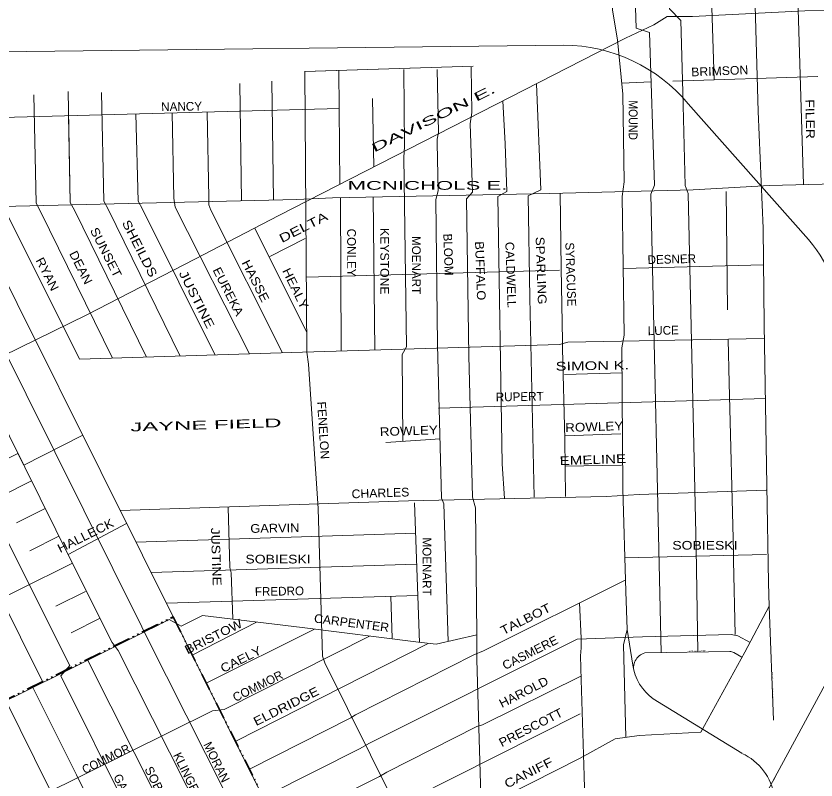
# Model space of a CAD drawing. Extents: x 34705 to 138605, y 34275 to 143551.
# Drawn here: x 95843 to 102735, y 126812 to 133396 of the extents above; entities that cross this region are included whole.
import ezdxf
from ezdxf.enums import TextEntityAlignment as Align

# ---------------------------------------------------------------- set-up
doc = ezdxf.new("R2010")
doc.units = 0
doc.header["$LTSCALE"] = 30
doc.linetypes.add('DASH_DOUBLE_DOT', pattern=[9.2, 5, -1.2, 0.3, -1.2, 0.3, -1.2])
for name, color, linetype, lineweight in [('1', 7, 'Continuous', 13), ('11', 7, 'Continuous', 13), ('50', 7, 'Continuous', 13), ('59', 7, 'DASH_DOUBLE_DOT', 106)]:
    doc.layers.add(name, color=color, linetype=linetype, lineweight=lineweight)
doc.layers.add('12', color=7, linetype='Continuous')

msp = doc.modelspace()

# ---------------------------------------------------------------- linework, layer by layer
at = {"layer": '1'}
for p, q in [((102549.39, 134581.2), (102627.53, 131943.02)), ((98327.75, 132918.07), (99781.24, 132964.59)), ((98330.03, 132918.14), (99781.24, 132964.59)), ((98625.01, 132927.58), (98631.65, 131943.94)), ((98048, 132833.55), (98061.13, 131808.84)), ((101061.68, 132816.44), (101314.5, 132828.78)), ((101502.89, 132835.92), (102751.71, 132874.45)), ((97772.33, 132814.31), (97785.63, 131802.55)), ((98913.49, 132686.05), (98926.92, 132095.21)), ((101960.33, 131884.41), (101973.15, 130864.72)), ((98637.77, 131830.64), (98644.22, 130508)), ((98920.06, 131836.21), (98932.87, 130516.62)), ((97899.81, 131568.1), (98347.97, 130668.5)), ((98028.7, 131323.65), (98332.77, 131480.08)), ((101075.91, 131220.45), (102283.32, 131251.08)), ((98345.8, 131145.49), (100526.42, 131206.32)), ((100567.68, 130307.94), (101064.21, 130321.13)), ((99481.71, 130016.81), (102299.09, 130099.57)), ((94897.78, 130008.58), (96075.01, 127654.96)), ((100570.04, 129777.26), (101054.19, 129795.2)), ((99029.95, 129721.33), (99496.07, 129753.64)), ((100573.75, 129516.97), (101058.54, 129525.79)), ((95721.67, 129261.64), (95976.32, 129390.62)), ((99275.71, 129200.52), (99317.93, 127998.54)), ((95847.62, 129027.04), (96094.58, 129152.13)), ((95961.44, 128786.29), (96212.84, 128913.63)), ((96876.15, 128861.4), (99284.83, 128940.69)), ((101084.6, 128726.26), (102309.57, 128756.68)), ((97006.36, 128600.16), (99294.27, 128671.97)), ((96185.82, 128311.29), (96442.1, 128437.3)), ((97138.31, 128335.44), (99303.76, 128401.89)), ((99073.35, 128394.82), (99083.38, 128033.33)), ((102367.68, 127328.44), (102332.17, 128310.71)), ((96316.78, 128079.72), (96568.08, 128207)), ((97360.79, 127889.1), (97915.38, 128173.24)), ((97481.37, 127646.97), (98415.73, 128112.08)), ((101157.23, 127802.13), (101109.27, 128110.29)), ((97737.66, 127147.84), (99394.8, 127989.84)), ((101259.02, 127906.69), (101992.73, 127919.08)), ((102027.16, 127909.59), (102097.27, 127871.32)), ((96460.12, 127843.12), (97659.84, 125468.45)), ((101333.46, 127512.66), (102094.78, 127042.89)), ((98232.79, 126139.68), (100704.52, 127382.49))]:
    msp.add_line(p, q, dxfattribs=at)
for points in [[(101951.16, 142542.84), (102026.05, 139982.57), (102027.19, 139747.46), (102070.92, 138206.13), (102096.57, 137212.1), (102088.55, 137181.64), (102088.55, 137040.55), (102101.37, 136527.5), (102127.02, 135937.49), (102139.84, 135437.27), (102152.66, 135020.41), (102203.95, 133878.88), (102210.36, 133484.48), (102236.01, 132573.81), (102280.88, 131566.95), (102287.29, 130736.46), (102312.94, 129351.22), (102325.76, 128511.11), (102332.17, 128310.71), (102120.61, 127913.09), (101741.51, 127224.19)], [(100686.61, 142506.77), (100763.07, 139892.78), (100750.25, 139726.04), (100764.21, 139657.68), (100807.95, 138116.35), (100833.59, 137122.31), (100846.42, 136910.68), (100878.47, 135865.34), (100910.53, 135087.76), (100948.99, 133965.46), (100981.05, 133446), (101025.93, 133189.47), (101070.8, 132721.32), (101083.62, 131967.78), (101064.39, 131839.52), (101083.62, 130646.68), (101062.79, 130537.65), (101070.8, 129322.37), (101096.45, 128437.36), (101109.27, 128110.29), (101077.21, 127975.62), (101097.94, 127180.93)], [(95349.32, 142354.53), (95401.65, 141128.32), (95400.24, 140999.04), (95387.42, 140890.02), (95432.3, 139735.66), (95451.53, 139575.33), (95560.52, 137037.34), (95573.34, 136928.31), (95675.92, 134412.77), (95682.33, 134348.64), (95703.17, 132562.59), (95727.2, 131801.04), (95752.85, 131717.67), (96389.41, 130437.7)], [(90104.12, 141802.04), (90220.45, 141642.8), (90630.68, 140864.96), (91512.35, 139205.15), (92694.04, 136986.48), (92755.27, 136888.48), (93165.5, 136080.02), (94792.8, 133011.51), (95209.51, 132197.05), (95491.6, 131639.1), (98371.75, 125860.89), (98410.22, 125771.11), (99474.45, 123667.62), (99570.62, 123609.9), (99859.12, 123007.06), (99871.94, 122930.11), (99923.24, 122823.63)], [(101012.58, 139829.49), (101029.14, 139139.23), (101082.02, 137220.12), (101062.79, 137143.16), (101184.6, 133292.08), (101299.99, 133253.61), (101344.87, 131938.91), (101312.82, 131861.96), (101402.37, 127909.11)], [(101345.73, 139838.97), (101362.51, 139139.23), (101415.39, 137239.36), (101357.69, 137162.4), (101473.09, 133458.83), (101569.26, 133356.22), (101588.49, 132740.56)], [(101686.97, 139848.67), (101702.3, 139209.78), (101748.77, 137239.36), (101710.3, 137168.81), (101787.23, 135177.54), (101787.23, 135074.93), (101857.44, 132846.86)], [(95130.25, 130321.18), (95381.61, 130325.96), (95576.64, 130393.64), (96452.28, 130819.66), (97383.65, 131301.42), (98108.05, 131675.68), (101094.19, 133205.57), (101336.98, 133321.03), (101452.41, 133392.7), (101671.32, 133392.7), (102639.49, 133440.47), (105214.69, 133516.12), (106171.95, 133548.83)], [(94232.64, 133482.78), (95119.76, 131760.95), (95164.64, 131671.17), (95177.46, 131645.52), (96927.67, 128132.74), (96972.55, 128036.55), (98146.33, 125708.92)], [(98330.03, 132918.14), (98349.32, 130499.17), (98362.14, 130396.56), (98445.49, 129152.42), (98483.95, 127879.42), (98503.19, 127821.7), (99879.07, 125050.88)], [(99182.76, 132936.16), (99189.17, 132269.2), (99182.76, 132179.41), (99208.4, 130544.07), (99169.93, 130479.94), (99176.34, 129736.01)], [(99471.25, 132936.16), (99484.08, 132391.05), (99471.25, 132333.33), (99471.25, 132301.26), (99480.86, 131890.82), (99458.43, 131813.87), (99474.45, 130563.31), (99509.72, 129242.2), (99528.95, 129190.9), (99564.89, 128005.86)], [(99762.95, 132955.4), (99769.36, 132564.2), (99756.54, 132468), (99775.77, 131878), (99724.48, 131820.28), (99743.72, 130467.11), (99775.77, 129248.61), (99801.42, 129158.83), (99814.24, 128067.01), (99814.24, 127848.96), (99929.64, 123858.4)], [(100326.11, 132812.06), (100365.59, 131897.24), (100256.6, 131845.93), (100269.42, 130967.33), (100307.89, 129248.61)], [(95996.47, 132718.12), (96015.7, 131781.8), (96054.17, 131711.26), (96673.76, 130446.63)], [(96290.94, 132745.63), (96310.61, 131788.21), (96349.07, 131717.67), (96967.29, 130455.85)], [(96579.87, 132737.36), (96599.11, 131801.04), (96637.57, 131730.49), (97257.6, 130464.97)], [(101588.49, 132740.56), (101607.72, 131935.71), (101633.37, 131865.17), (101703.89, 128806.11), (101716.07, 127914.4)], [(100037.35, 132664.12), (100057.86, 132294.85), (100070.68, 131884.41), (99993.75, 131839.52), (100032.21, 129537.21), (100050.6, 129236.8)], [(95061.76, 132493.51), (95189.67, 132557.48), (95695.48, 132563.3), (95724.55, 132522.59), (98630.08, 132598.19)], [(96874.42, 132552.51), (96894.01, 131801.04), (96932.48, 131730.49), (97557.09, 130474.37)], [(97188.76, 132560.69), (97201.74, 131826.69), (97214.57, 131749.73), (97853.59, 130483.68)], [(97490.05, 132568.53), (97503.06, 131833.1), (97503.06, 131768.97), (97522.3, 131724.08), (98137.83, 130492.6)], [(96295.22, 132537.44), (96310.61, 131788.21), (96349.07, 131717.67), (96967.29, 130455.85)], [(89151.86, 131581.25), (90043.44, 131623.47), (90222.81, 131655.13), (92165.54, 131723.74), (95067.12, 131739.57), (95420.59, 131739.57), (95721.29, 131755.4), (98262.81, 131813.45), (98568.79, 131829.28), (100441.63, 131866.22), (101676.12, 131897.89), (102335.57, 131934.83), (102900.06, 131950.66), (106145.2, 132049.31), (106275.51, 132066.69), (107380.6, 132092.9)], [(94731.9, 131962.97), (95512.95, 130409.57), (95517.24, 130316.41), (96318.63, 128700.3), (96671.23, 127998.07), (96722.52, 127927.52), (97903.51, 125588.89)], [(100532.11, 131868.54), (100538.69, 131223.86), (100551.51, 130595.37), (100551.51, 130531.24), (100570.74, 129748.84), (100577.15, 129255.03)], [(96389.41, 130437.7), (98311.05, 130498.04), (100525.34, 130564.93), (100596.11, 130586.71), (102289.51, 130616.89)], [(101979.56, 130608.2), (101985.98, 130236.24), (102024.44, 128780.46), (102024.44, 128703.5), (102037.83, 128065.55)], [(95131.5, 130138.02), (96305.8, 127799.26), (96228.87, 127709.48), (97384.45, 125389.53), (97653.72, 124838), (97660.13, 124818.77), (97807.58, 124652.02), (97945.42, 124408.33), (97983.89, 124363.43), (98567.3, 123196.24), (98592.94, 123119.29), (99163.52, 121977.75)], [(92031.01, 127728.04), (93759.06, 128587.98), (93811.76, 128481.61), (94481.31, 128812.57), (94426.71, 128922.17), (95859.1, 129627), (95908.95, 129526.46), (96411.7, 129779.99)], [(96739.51, 129135.51), (99224.35, 129218.36), (100928.22, 129256.38), (101210.57, 129273.76), (102305.23, 129308.53)], [(97669.75, 129162.04), (97685.77, 128644.19), (97695.39, 128597.69), (97709.82, 128201.68)], [(92783.26, 126916.28), (92904.03, 126982.73), (93966.1, 127504.16), (94843.56, 127934.34), (94939.13, 127990.83), (96329.05, 128679.54), (96291.19, 128755.63), (96795.84, 129022.52)], [(97859.28, 126908.85), (98728.06, 127347.73), (98767.15, 127373.8), (99787.96, 127890.89), (99870.49, 127925.65), (101091.12, 128533.99)], [(100698, 128338.07), (100711.78, 128034.94), (100711.78, 127951.57), (100705.37, 127881.03), (100711.78, 127675.81), (100737.43, 126848.51), (100788.72, 124975.88)], [(93161.76, 126203.92), (93402.49, 126330.93), (96243.37, 127734.46), (97162.1, 128195.06), (97266.35, 128138.57), (97448.79, 128229.82), (98308.88, 128125.53), (99310.14, 127999.52), (99462.17, 127982.14), (99814.28, 128063.42)], [(91804.4, 124602.41), (92258.1, 124821.03), (92523.21, 124902.16), (93277.23, 125281.76), (93553.22, 125429.66), (93553.22, 125434.59), (94282.6, 125789.54), (94282.6, 125863.49), (95554.1, 126489.58), (95692.09, 126494.51), (97536.49, 127409), (97635.06, 127418.86), (98887.4, 128052.72)], [(94580.43, 125251.39), (95217.74, 125572.62), (95306.45, 125478.96), (95927.41, 125784.61), (96060.48, 125720.52), (97920.9, 126635.01), (98014.54, 126684.31), (98807.99, 127083.63), (98881.91, 127128), (100678.27, 128025.23), (101240.09, 128044.95), (102003.97, 128064.67), (102063.11, 128054.81), (102166.81, 127997.19)], [(98106.89, 126404.8), (98975.66, 126843.68), (99036.47, 126878.44), (99814.02, 127273.86), (99861.81, 127286.89), (100708.86, 127708.39)], [(95987.8, 127608.19), (96363.5, 126856.53), (97169, 125225.82)], [(95754.45, 127497.84), (96126.29, 126747.51), (96164.76, 126676.96), (96932.73, 125109.03)], [(93365.26, 123330.55), (93956.1, 123637.65), (98379.23, 125824.05), (100702.91, 126999.82), (101003.53, 127167.44), (101210.52, 127197.01), (101741.51, 127224.19), (101741.31, 127223.78)]]:
    msp.add_lwpolyline(points, dxfattribs=at)
for centre, radius, start, end in [((101295.27, 127780.5), 131.28, 106.02889, 200.57915), ((101990.69, 127844.45), 74.66, 60.75806, 88.43815), ((101583.83, 127863.47), 430.99, 188.18156, 234.48459), ((101902.2, 126605.66), 476.88, 7.643, 66.0502)]:
    msp.add_arc(centre, radius, start, end, dxfattribs=at)
at = {"layer": '50'}
for p, q in [((95678.87, 133088.07), (100563.97, 133144.41)), ((101632.92, 132640.31), (102671.13, 131471.39)), ((102370.3, 126813.99), (102381.36, 126834.49)), ((102370.5, 126812.45), (102381.41, 126832.69))]:
    msp.add_line(p, q, dxfattribs=at)
for points in [[(102381.37, 126834.33), (103625.89, 129138.56), (106032.14, 133515.49), (107949.49, 136936.41), (108177.8, 137385.22), (110790.54, 142647.36)], [(95605.01, 114875.68), (95898.83, 115205.5), (96253.46, 115672.66), (96427.21, 115978.34), (97040.49, 117123.56), (97587.96, 118151.92), (98941.92, 120620.79), (100322.5, 123162.08), (102317.07, 126715.28), (102381.36, 126834.49)]]:
    msp.add_lwpolyline(points, dxfattribs=at)
for centre, radius, start, end in [((100556.78, 131743.75), 1400.67, 39.79829, 89.70596), ((101213, 130316.33), 1860.19, 10.55696, 38.38477)]:
    msp.add_arc(centre, radius, start, end, dxfattribs=at)
at = {"layer": '59', "lineweight": 35}
msp.add_line((91991.09, 125628.99), (97197.73, 128215.55), dxfattribs=at)
msp.add_lwpolyline([(91983.3, 125629.39), (97196.01, 128218.97), (98041.3, 126530.08), (101064.01, 126630.97), (101215.3, 121377.77), (100630.88, 121363.11), (101602.13, 119372.61), (97881.18, 117512.12), (95736.43, 121807.31), (94620.91, 121239.02)], close=True, dxfattribs=at)
msp.add_lwpolyline([(97196.01, 128218.97), (97196.01, 128218.97), (98041.3, 126530.08), (98041.31, 126530.08)], dxfattribs=at)

# ---------------------------------------------------------------- texts
at = {"layer": '11'}
for s, height, rotation, width, p in [('BRIMSON', 75, 2.298, 1.05, (101907.13, 132885.43)), ('DAVISON E.', 75, 26.403, 2.05, (99454.97, 132480.58)), ('MOUND', 75, 270, 0.9, (101122.46, 132498.53)), ('FILER', 75, 270.997, 1.2, (102647.36, 132506.9)), ('DELTA ', 75, 26.946, 1.4, (98352.83, 131550.32)), ('SHEILDS', 75, 296.947, 1.25, (96875.02, 131375.66)), ('SUNSET', 75, 296.944, 1.15, (96583.87, 131341.74)), ('KEYSTONE', 75, 270, 1.05, (98981.69, 131282.31)), ('BUFFALO', 75, 271.999, 1.1, (99806.39, 131198.96)), ('CALDWELL', 75, 271.999, 1.05, (100068.16, 131164.9)), ('SPARLING', 75, 272, 1.15, (100329.87, 131200.7)), ('DEAN', 75, 296.948, 1.1, (96367.88, 131211.71)), ('RYAN', 75, 296.949, 1.1, (96078.81, 131154.65)), ('HASSE', 75, 296.944, 1.15, (97873.36, 131096.41)), ('JUSTINE', 75, 296.947, 1.3, (97366.94, 130937.2)), ('EUREKA', 75, 296.947, 1.1, (97637.61, 131005.01)), ('HEALY', 75, 295.947, 1.15, (98216.92, 131031.44)), ('SIMON K. ', 75, 1.002, 1.4, (100827.91, 130345.74)), ('FENELON', 75, 273.694, 1.05, (98452.81, 129823.11)), ('JAYNE FIELD', 75, 1.665, 2.05, (97479.83, 129834.76)), ('ROWLEY ', 75, 1.999, 1.15, (99244.25, 129784.48)), ('ROWLEY ', 75, 2, 1.15, (100841.37, 129819.99)), ('EMELINE ', 75, 2, 1.3, (100831.96, 129535.87)), ('CHARLES', 75, 2.001, 1.05, (98983.78, 129248.21)), ('HALLECK', 75, 26.414, 1.15, (96458.5, 128884.39)), ('JUSTINE', 75, 271.998, 1.2, (97530.08, 128734.8)), ('GARVIN', 75, 1.002, 1.1, (98073.41, 128945.36)), ('TALBOT', 75, 26.769, 1.2, (100249.13, 128165.47)), ('CARPENTER', 75, 352.739, 1.05, (98729.24, 128129.11)), ('BRISTOW', 75, 26.56, 1.15, (97560.7, 128015.35)), ('CASMERE', 75, 26.77, 1.05, (100288.91, 127876.61)), ('CAELY', 75, 26.431, 1.15, (97796.77, 127818.09)), ('MT. ELLIOTT    ', 14.06, 1.539, 1.25, (101726.31, 127913.67)), ('HAROLD', 75, 26.992, 1.1, (100233.37, 127536.23)), ('ELDRIDGE', 75, 26.657, 1.2, (98186.42, 127414.28)), ('MT. ELLIOTT', 12.49, 91, 1.1, (102368.14, 127569.14)), ('PRESCOTT', 75, 26.994, 1.1, (100295.27, 127230.73)), ('CANIFF', 75, 26.919, 1.25, (100275.39, 126840.97))]:
    msp.add_text(s, height=height, rotation=rotation, dxfattribs=dict(at, width=width)).set_placement(p, align=Align.CENTER)
for s, height, rotation, p in [('NANCY', 75, 0.999, (97269.86, 132579.05)), ('CONLEY', 75, 270, (98695.92, 131357.06)), ('BLOOM', 75, 272, (99530.52, 131338.72)), ('MOENART', 75, 270, (99254.32, 131249.17)), ('SYRACUSE', 75, 271.998, (100584.71, 131167.93)), ('DESNER', 75, 1.498, (101493.52, 131263.3)), ('LUCE', 75, 1.677, (101420.34, 130649.01)), ('RUPERT', 75, 1.002, (100182.92, 130078.82)), ('MOENART', 75, 270, (99345.18, 128651.17)), ('FREDRO', 75, 0.998, (98112.87, 128401.75)), ('COMMOR', 75, 26.43, (97942.68, 127588.01)), ('COURT', 12.49, 91, (102365.56, 127713.49))]:
    msp.add_text(s, height=height, rotation=rotation, dxfattribs=at).set_placement(p, align=Align.CENTER)
for s, width, p in [('MCNICHOLS E.', 1.9, (99387.43, 131898.88)), ('SOBIESKI', 1.2, (101778.12, 128797.31)), ('SOBIESKI', 1.2, (98100.13, 128678.32))]:
    msp.add_text(s, height=75, dxfattribs=dict(at, width=width)).set_placement(p, align=Align.CENTER)
at = {"layer": '12'}
for s, rotation, width, p in [('COMMOR', 26.27, 0.95, (96634.7, 126960.22)), ('SOBIESKI', 296.27, 1.05, (97056.61, 126686.09))]:
    msp.add_text(s, height=75, rotation=rotation, dxfattribs=dict(at, width=width)).set_placement(p, align=Align.CENTER)
for s, rotation, p in [('MORAN', 296.268, (97536.76, 126950.36)), ('KLINGER', 296.269, (97291.47, 126828.74)), ('GALLAGHER', 296.268, (96814.23, 126566.09))]:
    msp.add_text(s, height=75, rotation=rotation, dxfattribs=at).set_placement(p, align=Align.CENTER)

doc.saveas('drawing.dxf')
